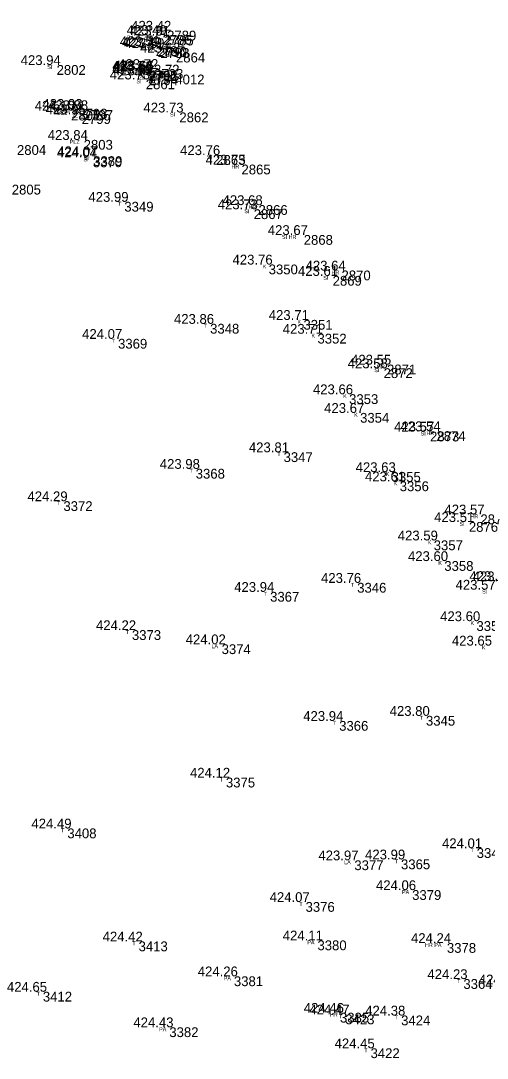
# Model space of a CAD drawing. Extents: x -639390 to -639075, y -1138747 to -1138358.
# Drawn here: x -639300.2 to -639264.6, y -1138437.1 to -1138357.7 of the extents above; entities that cross this region are included whole.
import ezdxf

# ---------------------------------------------------------------- set-up
doc = ezdxf.new("R2010")
doc.units = 0
for name, color, linetype in [('Vrstva 11', 7, 'Continuous'), ('Vrstva 12', 7, 'Continuous'), ('Vrstva 13', 7, 'Continuous'), ('Vrstva 57', 7, 'Continuous')]:
    doc.layers.add(name, color=color, linetype=linetype)

msp = doc.modelspace()

# ---------------------------------------------------------------- linework, layer by layer
at = {"layer": 'Vrstva 11'}
for p, q in [((-639289.32, -1138358.46), (-639289.32, -1138358.46)), ((-639289.67, -1138358.79), (-639289.67, -1138358.79)), ((-639289.52, -1138358.84), (-639289.52, -1138358.84)), ((-639290.19, -1138359.65), (-639290.19, -1138359.65)), ((-639290.03, -1138359.72), (-639290.03, -1138359.72)), ((-639289.84, -1138359.79), (-639289.84, -1138359.79)), ((-639288.64, -1138360.14), (-639288.64, -1138360.14)), ((-639297.77, -1138361.09), (-639297.77, -1138361.09)), ((-639290.77, -1138361.52), (-639290.77, -1138361.52)), ((-639290.74, -1138361.55), (-639290.74, -1138361.55)), ((-639290.64, -1138361.51), (-639290.64, -1138361.51)), ((-639290.31, -1138361.39), (-639290.31, -1138361.39)), ((-639290.95, -1138362.19), (-639290.95, -1138362.19)), ((-639290.77, -1138361.75), (-639290.77, -1138361.75)), ((-639290.71, -1138361.88), (-639290.71, -1138361.88)), ((-639288.69, -1138361.82), (-639288.69, -1138361.82)), ((-639296.66, -1138364.58), (-639296.66, -1138364.58)), ((-639296.11, -1138364.44), (-639296.11, -1138364.44)), ((-639295.85, -1138364.85), (-639295.85, -1138364.85)), ((-639295.68, -1138364.54), (-639295.68, -1138364.54)), ((-639288.38, -1138364.72), (-639288.38, -1138364.72)), ((-639295.7, -1138366.82), (-639295.7, -1138366.82)), ((-639294.97, -1138368.07), (-639294.97, -1138368.07)), ((-639285.56, -1138367.98), (-639285.56, -1138367.98)), ((-639295, -1138368.16), (-639295, -1138368.16)), ((-639283.63, -1138368.71), (-639283.63, -1138368.71)), ((-639292.59, -1138371.56), (-639292.59, -1138371.56)), ((-639282.33, -1138371.81), (-639282.33, -1138371.81)), ((-639282.7, -1138372.13), (-639282.7, -1138372.13)), ((-639278.87, -1138374.1), (-639278.87, -1138374.1)), ((-639281.55, -1138376.36), (-639281.55, -1138376.36)), ((-639275.98, -1138376.82), (-639275.98, -1138376.82)), ((-639276.66, -1138377.23), (-639276.66, -1138377.23)), ((-639278.89, -1138380.6), (-639278.89, -1138380.6)), ((-639286.03, -1138380.9), (-639286.03, -1138380.9)), ((-639293.07, -1138382.05), (-639293.07, -1138382.05)), ((-639277.82, -1138381.66), (-639277.82, -1138381.66)), ((-639272.76, -1138384.3), (-639272.76, -1138384.3)), ((-639272.5, -1138384.02), (-639272.5, -1138384.02)), ((-639275.4, -1138386.29), (-639275.4, -1138386.29)), ((-639274.56, -1138387.72), (-639274.56, -1138387.72)), ((-639269.21, -1138389.15), (-639269.21, -1138389.15)), ((-639268.72, -1138389.12), (-639268.72, -1138389.12)), ((-639280.41, -1138390.73), (-639280.41, -1138390.73)), ((-639287.13, -1138392), (-639287.13, -1138392)), ((-639272.15, -1138392.25), (-639272.15, -1138392.25)), ((-639271.53, -1138392.96), (-639271.53, -1138392.96)), ((-639297.25, -1138394.48), (-639297.25, -1138394.48)), ((-639265.36, -1138395.49), (-639265.36, -1138395.49)), ((-639266.24, -1138396.07), (-639266.24, -1138396.07)), ((-639268.93, -1138397.48), (-639268.93, -1138397.48)), ((-639268.12, -1138399.06), (-639268.12, -1138399.06)), ((-639281.44, -1138401.42), (-639281.44, -1138401.42)), ((-639274.78, -1138400.73), (-639274.78, -1138400.73)), ((-639265.66, -1138403.66), (-639265.66, -1138403.66)), ((-639292.01, -1138404.35), (-639292.01, -1138404.35)), ((-639285.15, -1138405.43), (-639285.15, -1138405.43)), ((-639264.79, -1138405.53), (-639264.79, -1138405.53)), ((-639269.52, -1138410.91), (-639269.52, -1138410.91)), ((-639276.16, -1138411.3), (-639276.16, -1138411.3)), ((-639284.82, -1138415.64), (-639284.82, -1138415.64)), ((-639296.95, -1138419.53), (-639296.95, -1138419.53)), ((-639265.64, -1138421.04), (-639265.64, -1138421.04)), ((-639275, -1138421.97), (-639275, -1138421.97)), ((-639271.43, -1138421.9), (-639271.43, -1138421.9)), ((-639270.58, -1138424.25), (-639270.58, -1138424.25)), ((-639278.73, -1138425.16), (-639278.73, -1138425.16)), ((-639291.5, -1138428.18), (-639291.5, -1138428.18)), ((-639277.82, -1138428.1), (-639277.82, -1138428.1)), ((-639267.92, -1138428.3), (-639267.92, -1138428.3)), ((-639284.21, -1138430.85), (-639284.21, -1138430.85)), ((-639266.66, -1138431.06), (-639266.66, -1138431.06)), ((-639298.82, -1138432.03), (-639298.82, -1138432.03)), ((-639276.1, -1138433.64), (-639276.1, -1138433.64)), ((-639275.69, -1138433.77), (-639275.69, -1138433.77)), ((-639271.42, -1138433.85), (-639271.42, -1138433.85)), ((-639289.15, -1138434.75), (-639289.15, -1138434.75)), ((-639273.76, -1138436.36), (-639273.76, -1138436.36))]:
    msp.add_line(p, q, dxfattribs=at)

# ---------------------------------------------------------------- texts
at = {"layer": 'Vrstva 12'}
for s, p in [('423.42 ', (-639291.789, -1138358.46)), ('423.49 ', (-639292.139, -1138358.79)), ('423.51 ', (-639291.895, -1138358.84)), ('423.59 ', (-639292.659, -1138359.65)), ('423.49 ', (-639292.499, -1138359.72)), ('423.59 ', (-639292.309, -1138359.79)), ('423.62 ', (-639291.109, -1138360.14)), ('423.94 ', (-639300.239, -1138361.09)), ('423.74 ', (-639293.239, -1138361.52)), ('423.68 ', (-639293.209, -1138361.55)), ('423.66 ', (-639293.126, -1138361.51)), ('423.72 ', (-639292.779, -1138361.39)), ('423.73 ', (-639293.419, -1138362.19)), ('423.69 ', (-639293.239, -1138361.75)), ('423.74 ', (-639293.179, -1138361.88)), ('423.72 ', (-639291.159, -1138361.82)), ('424.10 ', (-639299.159, -1138364.58)), ('423.93 ', (-639298.579, -1138364.44)), ('423.95 ', (-639298.32, -1138364.85)), ('423.88 ', (-639298.149, -1138364.54)), ('423.73 ', (-639290.849, -1138364.72)), ('423.84 ', (-639298.169, -1138366.82)), ('423.76 ', (-639288.046, -1138367.98)), ('424.04 ', (-639297.469, -1138368.16)), ('424.07 ', (-639297.439, -1138368.07)), ('423.75 ', (-639286.1, -1138368.71)), ('423.99 ', (-639295.059, -1138371.56)), ('423.68 ', (-639284.799, -1138371.81)), ('423.73 ', (-639285.169, -1138372.13)), ('423.67 ', (-639281.339, -1138374.1)), ('423.76 ', (-639284.036, -1138376.36)), ('423.61 ', (-639279.035, -1138377.23)), ('423.64 ', (-639278.449, -1138376.82)), ('423.71 ', (-639281.265, -1138380.6)), ('423.86 ', (-639288.516, -1138380.9)), ('424.07 ', (-639295.539, -1138382.05)), ('423.71 ', (-639280.195, -1138381.66)), ('423.58 ', (-639275.229, -1138384.3)), ('423.55 ', (-639274.97, -1138384.02)), ('423.66 ', (-639277.886, -1138386.29)), ('423.67 ', (-639277.029, -1138387.72)), ('423.57 ', (-639271.679, -1138389.15)), ('423.54 ', (-639271.189, -1138389.12)), ('423.81 ', (-639282.785, -1138390.73)), ('423.98 ', (-639289.599, -1138392)), ('423.63 ', (-639274.619, -1138392.25)), ('423.61 ', (-639273.905, -1138392.96)), ('424.29 ', (-639299.719, -1138394.48)), ('423.57 ', (-639267.829, -1138395.49)), ('423.51 ', (-639268.615, -1138396.07)), ('423.59 ', (-639271.399, -1138397.48)), ('423.60 ', (-639270.619, -1138399.06)), ('423.58 ', (-639265.919, -1138400.59)), ('423.66 ', (-639265.666, -1138400.61)), ('423.76 ', (-639277.266, -1138400.73)), ('423.57 ', (-639266.979, -1138401.25)), ('423.94 ', (-639283.909, -1138401.42)), ('423.60 ', (-639268.159, -1138403.66)), ('424.22 ', (-639294.479, -1138404.35)), ('424.02 ', (-639287.619, -1138405.43)), ('423.65 ', (-639267.26, -1138405.53)), ('423.80 ', (-639272.019, -1138410.91)), ('423.94 ', (-639278.629, -1138411.3)), ('424.12 ', (-639287.289, -1138415.64)), ('424.49 ', (-639299.419, -1138419.53)), ('424.01 ', (-639268.015, -1138421.04)), ('423.97 ', (-639277.469, -1138421.97)), ('423.99 ', (-639273.899, -1138421.9)), ('424.06 ', (-639273.066, -1138424.25)), ('424.07 ', (-639281.199, -1138425.16)), ('424.42 ', (-639293.969, -1138428.18)), ('424.11 ', (-639280.195, -1138428.1)), ('424.24 ', (-639270.389, -1138428.3)), ('424.26 ', (-639286.696, -1138430.85)), ('424.23 ', (-639269.129, -1138431.06)), ('424.15 ', (-639265.2, -1138431.47)), ('424.65 ', (-639301.29, -1138432.03)), ('424.46 ', (-639278.586, -1138433.64)), ('424.47 ', (-639278.159, -1138433.77)), ('424.38 ', (-639273.889, -1138433.85)), ('424.43 ', (-639291.619, -1138434.75)), ('424.45 ', (-639276.23, -1138436.36))]:
    msp.add_text(s, height=0.75, dxfattribs=at).set_placement(p)
at = {"layer": 'Vrstva 13'}
for s, p in [(' 2789', (-639289.32, -1138359.21)), (' 2786', (-639289.67, -1138359.54)), (' 2785', (-639289.52, -1138359.59)), (' 2787', (-639290.19, -1138360.4)), (' 2790', (-639290.03, -1138360.47)), (' 2788', (-639289.84, -1138360.54)), (' 2864', (-639288.64, -1138360.89)), (' 2802', (-639297.77, -1138361.84)), (' 2795', (-639290.77, -1138362.27)), (' 2796', (-639290.77, -1138362.5)), (' 2792', (-639290.74, -1138362.3)), (' 2791', (-639290.64, -1138362.26)), (' 2793', (-639290.31, -1138362.14)), (' 2861', (-639290.95, -1138362.94)), (' 2794', (-639290.71, -1138362.63)), (' 4012', (-639288.69, -1138362.57)), (' 2801', (-639296.66, -1138365.33)), (' 2798', (-639296.11, -1138365.19)), (' 2799', (-639295.85, -1138365.6)), (' 2797', (-639295.68, -1138365.29)), (' 2862', (-639288.38, -1138365.47)), (' 2804', (-639300.8, -1138367.97)), (' 2803', (-639295.7, -1138367.57)), (' 3389', (-639294.97, -1138368.82)), (' 2863', (-639285.56, -1138368.73)), (' 3370', (-639295, -1138368.91)), (' 2865', (-639283.63, -1138369.46)), (' 2805', (-639301.2, -1138371)), (' 3349', (-639292.59, -1138372.31)), (' 2866', (-639282.33, -1138372.56)), (' 2867', (-639282.7, -1138372.88)), (' 2868', (-639278.87, -1138374.85)), (' 3350', (-639281.55, -1138377.11)), (' 2870', (-639275.98, -1138377.57)), (' 2869', (-639276.66, -1138377.98)), (' 3351', (-639278.89, -1138381.35)), (' 3348', (-639286.03, -1138381.65)), (' 3369', (-639293.07, -1138382.8)), (' 3352', (-639277.82, -1138382.41)), (' 2872', (-639272.76, -1138385.05)), (' 2871', (-639272.5, -1138384.77)), (' 3353', (-639275.4, -1138387.04)), (' 3354', (-639274.56, -1138388.47)), (' 2873', (-639269.21, -1138389.9)), (' 2874', (-639268.72, -1138389.87)), (' 3347', (-639280.41, -1138391.48)), (' 3368', (-639287.13, -1138392.75)), (' 3355', (-639272.15, -1138393)), (' 3356', (-639271.53, -1138393.71)), (' 3372', (-639297.25, -1138395.23)), (' 2875', (-639265.36, -1138396.24)), (' 2876', (-639266.24, -1138396.82)), (' 3357', (-639268.93, -1138398.23)), (' 3358', (-639268.12, -1138399.81)), (' 3367', (-639281.44, -1138402.17)), (' 3346', (-639274.78, -1138401.48)), (' 3359', (-639265.66, -1138404.41)), (' 3373', (-639292.01, -1138405.1)), (' 3374', (-639285.15, -1138406.18)), (' 3345', (-639269.52, -1138411.66)), (' 3366', (-639276.16, -1138412.05)), (' 3375', (-639284.82, -1138416.39)), (' 3408', (-639296.95, -1138420.28)), (' 3344', (-639265.64, -1138421.79)), (' 3377', (-639275, -1138422.72)), (' 3365', (-639271.43, -1138422.65)), (' 3379', (-639270.58, -1138425)), (' 3376', (-639278.73, -1138425.91)), (' 3413', (-639291.5, -1138428.93)), (' 3380', (-639277.82, -1138428.85)), (' 3378', (-639267.92, -1138429.05)), (' 3381', (-639284.21, -1138431.6)), (' 3364', (-639266.66, -1138431.81)), (' 3412', (-639298.82, -1138432.78)), (' 3385', (-639276.1, -1138434.39)), (' 3423', (-639275.69, -1138434.52)), (' 3424', (-639271.42, -1138434.6)), (' 3382', (-639289.15, -1138435.5)), (' 3422', (-639273.76, -1138437.11))]:
    msp.add_text(s, height=0.75, dxfattribs=at).set_placement(p)
at = {"layer": 'Vrstva 57'}
for s, p in [('PA', (-639289.82, -1138358.76)), ('PA ZL ZLA', (-639292.12, -1138359.14)), ('ZLA', (-639290.47, -1138359.09)), ('ZLA', (-639290.99, -1138359.95)), ('PA', (-639290.53, -1138360.02)), ('ZL', (-639290.315, -1138360.09)), ('HR', (-639289.129, -1138360.44)), ('SI', (-639298.208, -1138361.39)), ('ZLA', (-639291.57, -1138361.82)), ('ZLA', (-639291.54, -1138361.85)), ('PA', (-639291.14, -1138361.81)), ('ZL', (-639290.785, -1138361.69)), ('SI', (-639291.388, -1138362.49)), ('PA', (-639291.27, -1138362.05)), ('ZL', (-639291.185, -1138362.18)), ('STAN', (-639289.779, -1138362.12)), ('ZLA SI', (-639297.748, -1138364.74)), ('BZL', (-639297.435, -1138364.88)), ('ZL', (-639296.325, -1138365.15)), ('PA', (-639296.18, -1138364.84)), ('SI', (-639288.818, -1138365.02)), ('PLZ', (-639296.489, -1138367.12)), ('SI', (-639295.408, -1138368.37)), ('SI', (-639285.998, -1138368.28)), ('SI', (-639295.438, -1138368.46)), ('HR', (-639284.119, -1138369.01)), ('T', (-639292.79, -1138371.86)), ('HR', (-639282.819, -1138372.11)), ('SI', (-639283.138, -1138372.43)), ('SI HR', (-639280.259, -1138374.4)), ('K', (-639281.725, -1138376.66)), ('HR', (-639276.469, -1138377.12)), ('SI', (-639277.098, -1138377.53)), ('K', (-639279.065, -1138380.9)), ('T', (-639286.23, -1138381.2)), ('T', (-639293.27, -1138382.35)), ('K', (-639277.995, -1138381.96)), ('SI', (-639273.198, -1138384.6)), ('HR', (-639272.989, -1138384.32)), ('K', (-639275.575, -1138386.59)), ('K', (-639274.735, -1138388.02)), ('SI', (-639269.648, -1138389.45)), ('HR', (-639269.209, -1138389.42)), ('T', (-639280.61, -1138391.03)), ('T', (-639287.33, -1138392.3)), ('K', (-639272.325, -1138392.55)), ('K', (-639271.705, -1138393.26)), ('T', (-639297.45, -1138394.78)), ('HR', (-639265.849, -1138395.79)), ('SI', (-639266.678, -1138396.37)), ('K', (-639269.105, -1138397.78)), ('K', (-639268.295, -1138399.36)), ('T', (-639281.64, -1138401.72)), ('T', (-639274.98, -1138401.03)), ('SI', (-639264.948, -1138401.55)), ('K', (-639265.835, -1138403.96)), ('T', (-639292.21, -1138404.65)), ('LA', (-639285.65, -1138405.73)), ('K', (-639264.965, -1138405.83)), ('T', (-639269.72, -1138411.21)), ('T', (-639276.36, -1138411.6)), ('T', (-639285.02, -1138415.94)), ('T', (-639297.15, -1138419.83)), ('T', (-639265.84, -1138421.34)), ('LA', (-639275.5, -1138422.27)), ('T', (-639271.63, -1138422.2)), ('PA', (-639271.08, -1138424.55)), ('T', (-639278.93, -1138425.46)), ('T', (-639291.7, -1138428.48)), ('PA', (-639278.32, -1138428.4)), ('HR PA', (-639269.32, -1138428.6)), ('PA', (-639284.71, -1138431.15)), ('T', (-639266.86, -1138431.36)), ('T', (-639299.02, -1138432.33)), ('HR', (-639276.589, -1138433.94)), ('T', (-639275.89, -1138434.07)), ('T', (-639271.62, -1138434.15)), ('PA', (-639289.65, -1138435.05)), ('T', (-639273.96, -1138436.66))]:
    msp.add_text(s, height=0.3, dxfattribs=at).set_placement(p)

doc.saveas('drawing.dxf')
